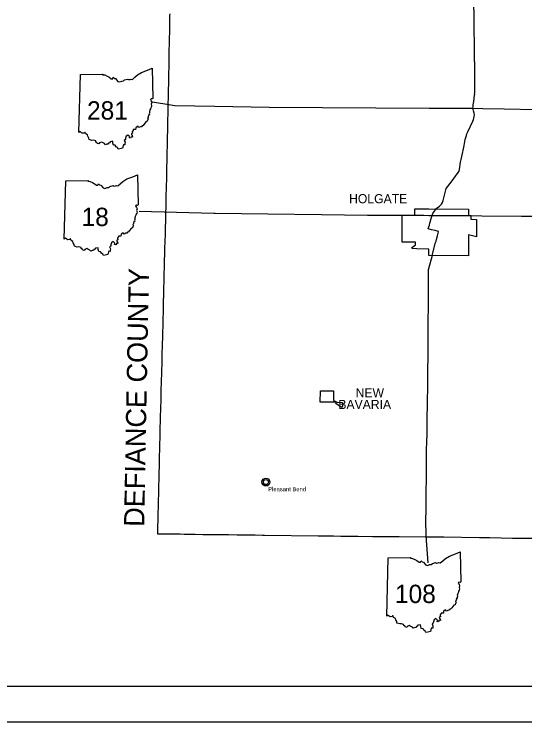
# Model space of a CAD drawing. Extents: x -62 to 810, y 0 to 440.
# Drawn here: x 166.9 to 310.9, y 0 to 199.3 of the extents above; entities that cross this region are included whole.
import ezdxf

# ---------------------------------------------------------------- set-up
doc = ezdxf.new("R2010")
doc.units = 0
for name, color, linetype in [('DV_X_Corp_Line', 7, 'Continuous'), ('GM_X_Adjacent_County_Text', 7, 'Continuous'), ('GM_X_Corporation_Text', 7, 'Continuous'), ('GM_X_County', 7, 'Continuous'), ('GM_X_State_Route', 7, 'Continuous'), ('PV_P_Text', 7, 'Continuous'), ('SH_Border', 7, 'Continuous'), ('SH_Cut_Line', 7, 'Continuous')]:
    doc.layers.add(name, color=color, linetype=linetype)

msp = doc.modelspace()

# ---------------------------------------------------------------- linework, layer by layer
at = {"layer": 'DV_X_Corp_Line'}
for points in [[(279.19, 133.31), (278.92, 133.53), (280.1, 134.39), (280.05, 135.06), (276.3, 135.11), (276.33, 142.7), (279.86, 142.69), (279.86, 144.51), (283.8, 144.52), (295.06, 144.43), (295.06, 142.58), (295.63, 142.57), (295.63, 141.54), (297.23, 141.51), (297.23, 136.6), (295.05, 137.18), (295.04, 135.75), (295.06, 131.26), (283.85, 131.34), (283.82, 133.16), (280.44, 133.26)], [(253.26, 93.23), (257.01, 93.23), (257.01, 90.5), (257.59, 90.25), (257.75, 90.17), (258, 90.01), (259.54, 89.99), (259.51, 88.92), (259.19, 88.57), (257.59, 89.68), (257.82, 90.01), (253.23, 90.06)]]:
    msp.add_lwpolyline(points, close=True, dxfattribs=at)
for radius in [1.12, 0.71]:
    msp.add_circle((237.91, 67.55), radius, dxfattribs=at)
at = {"layer": 'GM_X_County'}
msp.add_lwpolyline([(210.79, 199.39), (210.78, 198.9), (210.78, 198.36), (210.77, 197.7), (210.75, 196.78), (210.73, 195.73), (210.73, 195.48), (210.74, 195.3), (210.75, 195.11), (210.59, 188.38), (210.59, 188.18), (210.59, 187.72), (210.58, 187.41), (210.56, 186.61), (210.55, 186.35), (210.55, 186.22), (210.55, 186.05), (210.54, 185.84), (210.52, 185.04), (210.52, 184.66), (210.51, 184.14), (210.49, 183.01), (210.46, 181.7), (210.44, 180.62), (210.43, 179.89), (210.41, 179.2), (210.4, 178.55), (210.37, 177.22), (210.35, 176.42), (210.33, 175.26), (210.31, 174.68), (210.29, 173.89), (210.28, 172.95), (210.25, 171.58), (210.24, 171.06), (210.21, 169.71), (210.19, 168.69), (210.18, 168.07), (210.16, 167.47), (210.14, 166.03), (210.12, 165.32), (210.09, 163.95), (210.08, 163.49), (210.07, 163.16), (210.06, 162.58), (210.04, 161.51), (210.03, 161.1), (210.02, 160.71), (210.01, 160.11), (210, 159.66), (209.99, 159.15), (209.98, 158.78), (209.97, 158.67), (209.97, 158.58), (209.97, 158.57), (209.97, 158.47), (209.97, 158.39), (209.97, 158.35), (209.97, 158.3), (209.96, 158.18), (209.96, 158.13), (209.96, 157.88), (209.92, 156.28), (209.91, 155.64), (209.9, 155.31), (209.89, 154.56), (209.86, 152.94), (209.85, 152.29), (209.83, 151.52), (209.81, 151.22), (209.81, 151.12), (209.81, 151.04), (209.79, 150.53), (209.76, 149.75), (209.75, 148.82), (209.73, 148.21), (209.71, 146.96), (209.7, 146.22), (209.67, 144.67), (209.64, 143.65), (209.64, 143.28), (209.63, 142.74), (209.62, 142.38), (209.59, 141.49), (209.57, 140.57), (209.55, 139.74), (209.53, 139.21), (209.52, 138.71), (209.5, 138.14), (209.49, 137.47), (209.47, 136.51), (209.45, 136.09), (209.42, 135.28), (209.37, 133.38), (209.33, 131.98), (209.31, 131.42), (209.28, 130.25), (209.24, 128.79), (209.23, 128.54), (209.22, 128.38), (209.21, 128.01), (209.2, 127.47), (209.18, 126.79), (209.15, 125.69), (209.13, 124.51), (209.12, 123.95), (209.09, 122.47), (209.05, 120.78), (209.03, 120.05), (209.02, 119.65), (209.01, 119.57), (209.01, 119.46), (209, 119.11), (208.98, 118.08), (208.96, 117.38), (208.94, 116.4), (208.92, 115.39), (208.89, 113.53), (208.85, 111.96), (208.82, 111.23), (208.78, 109.94), (208.73, 108.04), (208.69, 106.64), (208.67, 106.03), (208.67, 105.86), (208.65, 105.21), (208.62, 104.3), (208.57, 101.83), (208.54, 100.63), (208.51, 99.13), (208.49, 98.5), (208.48, 98.3), (208.45, 97.36), (208.43, 96.8), (208.43, 96.79), (208.41, 96.31), (208.38, 95.21), (208.34, 93.86), (208.31, 92.54), (208.26, 90.67), (208.25, 90.53), (208.2, 88.43), (208.17, 87.47), (208.15, 86.57), (208.13, 85.92), (208.1, 85.18), (208.08, 84.09), (208.06, 83.39), (208.06, 83.15), (208.06, 82.92), (208.05, 82.57), (208.04, 82.18), (208.03, 81.98), (208.03, 81.74), (208.02, 81.51), (208.01, 81.12), (208, 80.56), (207.99, 80.24), (207.97, 79.66), (207.97, 79.36), (207.96, 78.96), (207.95, 78.4), (207.93, 77.97), (207.93, 77.81), (207.92, 77.27), (207.9, 76.7), (207.89, 76.34), (207.88, 75.96), (207.87, 75.58), (207.87, 75.49), (207.87, 75.14), (207.86, 74.74), (207.85, 74.31), (207.84, 73.91), (207.83, 73.5), (207.81, 72.78), (207.8, 72.4), (207.79, 71.89), (207.78, 71.45), (207.77, 70.8), (207.75, 70.16), (207.73, 69.5), (207.72, 68.99), (207.72, 68.66), (207.71, 68.46), (207.7, 68.22), (207.7, 68.13), (207.7, 68.11), (207.7, 68.06), (207.7, 68.03), (207.7, 67.75), (207.68, 67.08), (207.67, 66.71), (207.66, 66.34), (207.65, 65.82), (207.65, 65.64), (207.64, 65.45), (207.63, 65.13), (207.62, 64.52), (207.61, 64.12), (207.6, 63.67), (207.58, 62.94), (207.57, 62.5), (207.56, 62.16), (207.55, 61.91), (207.54, 61.3), (207.52, 60.76), (207.5, 59.92), (207.49, 59.57), (207.47, 58.74), (207.47, 58.62), (207.45, 57.88), (207.44, 57.59), (207.42, 56.92), (207.42, 56.63), (207.42, 56.42), (207.41, 56.19), (207.4, 55.71), (207.4, 55.52), (207.38, 54.94), (207.37, 54.55), (207.36, 53.88), (207.35, 53.35), (207.34, 52.98), (207.91, 52.98), (210.72, 52.94), (213.71, 52.91), (214.91, 52.89), (215.86, 52.87), (218.02, 52.84), (220.17, 52.81), (221.71, 52.78), (225.59, 52.74), (226.06, 52.74), (227.37, 52.73), (229.8, 52.7), (230.97, 52.69), (231.58, 52.68), (232.28, 52.67), (234.9, 52.65), (236.95, 52.61), (237.54, 52.61), (252.62, 52.42), (256.97, 52.37), (259.07, 52.34), (263.51, 52.28), (263.59, 52.28), (263.67, 52.28), (263.82, 52.28), (267.99, 52.23), (275.46, 52.17), (283.06, 52.11), (284.18, 52.11), (288.1, 52.08), (298.1, 51.96), (301, 51.9), (304.18, 51.82), (307.45, 51.77), (308.29, 51.76), (310.77, 51.73), (313.34, 51.7)], dxfattribs=at)
at = {"layer": 'GM_X_State_Route'}
msp.add_line((296.73, 185.88), (296.75, 177.12), dxfattribs=at)
for points in [[(296.73, 185.88), (296.73, 187.78), (296.61, 198.1), (296.52, 202.86), (296.5, 204.59), (296.42, 211.89), (296.39, 214.54), (296.33, 217.94), (296.33, 217.94)], [(296.28, 172.8), (296.33, 173.2), (296.37, 173.8), (296.49, 174.76), (296.74, 176.48), (296.77, 176.81), (296.75, 177.12)], [(205.99, 174.64), (211.07, 173.75), (212.25, 173.57), (223.56, 173.38), (238.86, 173.11), (253.82, 173.03), (268.89, 172.94), (283.91, 172.86), (296.28, 172.8)], [(286.02, 144.55), (286.23, 144.77), (286.82, 145.22), (287.37, 145.84), (287.66, 146.23), (287.87, 146.81), (288.76, 150.18), (290.14, 151.97), (292.08, 154.69), (292.35, 155.11), (292.49, 155.55), (292.77, 157.65), (292.93, 158.34), (293.33, 160.07), (293.65, 161.39), (293.81, 162.31), (294.1, 164.02), (294.27, 164.56), (294.45, 165.1), (294.58, 165.66), (294.83, 166.22), (296.25, 169.15), (296.42, 169.62), (296.52, 170.04), (296.62, 170.51), (296.67, 171.02), (296.6, 171.48), (296.44, 172.08), (296.28, 172.8)], [(296.28, 172.8), (299.02, 172.75), (305.07, 172.65), (314.15, 172.51), (329.25, 172.33), (342.44, 172.14)], [(202.18, 143.84), (223.28, 143.31), (223.64, 143.3), (238.42, 143.05), (253.55, 142.88), (266.57, 142.73), (268.03, 142.74), (268.67, 142.73), (275.77, 142.7)], [(284.16, 140.45), (284.24, 140.75), (284.54, 141.77), (284.77, 142.66), (284.92, 143.14), (285.11, 143.5), (285.67, 144.17), (286.01, 144.55), (286.02, 144.55)], [(275.77, 142.7), (276.37, 142.7)], [(276.37, 142.7), (277.35, 142.69), (277.42, 142.69)], [(277.42, 142.69), (279.53, 142.68), (279.82, 142.68)], [(279.82, 142.68), (280.51, 142.68), (281.53, 142.67), (282.44, 142.67), (283.87, 142.66), (284.77, 142.66), (285.76, 142.65), (286.79, 142.64), (287.79, 142.64), (290.03, 142.62), (291.71, 142.61)], [(291.71, 142.61), (295.18, 142.58)], [(295.18, 142.58), (295.79, 142.57)], [(295.79, 142.57), (298.8, 142.55), (309.97, 142.42), (314.08, 142.4), (342.7, 141.81)], [(283.69, 138.83), (283.86, 139.43), (283.99, 139.85), (284.16, 140.45)], [(286.56, 138), (286.58, 138.1), (285.59, 138.35), (284.62, 138.6), (283.69, 138.83)], [(284.85, 131.48), (284.85, 131.48), (284.9, 131.68), (285.76, 134.98), (285.87, 135.4), (286, 135.87), (286.27, 136.9), (286.56, 138), (286.56, 138)], [(283.62, 44.8), (283.04, 52.41), (283.01, 57), (283.04, 59.53), (283.07, 62.43), (283.13, 66.28), (283.14, 67.07), (283.15, 69.02), (283.18, 73.51), (283.22, 77.27), (283.25, 78.17), (283.33, 81.65), (283.34, 82.25), (283.39, 85.54), (283.46, 89.35), (283.47, 89.75), (283.53, 94.82), (283.56, 97.33), (283.64, 104.63), (283.68, 108.93), (283.69, 112.99), (283.71, 116.92), (283.75, 121.64), (283.79, 127.3), (283.79, 127.41), (283.84, 127.65), (284.85, 131.48)]]:
    msp.add_lwpolyline(points, dxfattribs=at)
at = {"layer": 'PV_P_Text'}
for p, q in [((185.18, 165.98), (185.64, 182.36)), ((185.18, 165.98), (185.64, 182.36)), ((181.04, 135.99), (181.5, 152.36)), ((181.04, 135.99), (181.5, 152.36)), ((271.96, 29.81), (272.42, 46.18)), ((271.96, 29.81), (272.42, 46.18))]:
    msp.add_line(p, q, dxfattribs=at)
for points in [[(185.64, 182.36), (191.99, 182.46), (191.89, 182.27), (192.49, 182.22), (193.13, 181.87), (193.67, 181.65), (194.33, 181.13), (194.72, 181.14), (194.89, 181.57), (195.19, 181.24), (195.55, 181.18), (196.17, 180.39), (196.68, 180.22), (197.29, 180.49), (197.75, 180.54), (198.08, 180.8), (198.95, 181.03), (199.2, 180.89), (199.66, 180.92), (199.89, 181.02), (200.29, 180.93), (201, 181.53), (201.73, 182.23), (202.85, 182.89), (204.53, 183.52), (205.86, 184.08), (206.05, 175.58)], [(185.64, 182.36), (191.99, 182.46), (191.89, 182.27), (192.49, 182.22), (193.13, 181.87), (193.67, 181.65), (194.33, 181.13), (194.72, 181.14), (194.89, 181.57), (195.19, 181.24), (195.55, 181.18), (196.17, 180.39), (196.68, 180.22), (197.29, 180.49), (197.75, 180.54), (198.08, 180.8), (198.95, 181.03), (199.2, 180.89), (199.66, 180.92), (199.89, 181.02), (200.29, 180.93), (201, 181.53), (201.73, 182.23), (202.85, 182.89), (204.53, 183.52), (205.86, 184.08), (206.05, 175.58)], [(206.05, 175.58), (205.85, 175.46), (205.55, 175.52), (205.34, 175.28), (205.6, 174.88), (205.72, 174.46), (205.61, 174), (205.71, 173.62), (205.64, 173.3), (205.45, 172.98), (205.38, 172.68), (205.22, 172.36), (205.24, 172.18), (205.08, 172.04), (205.11, 171.51), (205.03, 171.21), (205.06, 170.96), (204.81, 170.89), (204.86, 170.68), (204.7, 170.52), (204.74, 170.24), (204.56, 170.06), (204.73, 169.71), (204.59, 169.59), (204.47, 169.16), (204.15, 169.07), (203.5, 168.28), (203.28, 167.98), (203.02, 167.9), (202.88, 167.6), (202.56, 167.6), (202.09, 167.38), (201.78, 167.75), (201.24, 167.31), (201.18, 166.8), (200.49, 166.81), (200.52, 166.55), (200.37, 166.48), (200.23, 166.22), (200.31, 165.76), (199.99, 165.64), (200.03, 165.38), (200.23, 165.21), (200.32, 164.7), (199.98, 164.81), (199.7, 164.38), (199.42, 164.48), (199.51, 164.84), (199.03, 165.28), (198.57, 164.93), (198.33, 164.37), (198.33, 163.99), (197.99, 163.77), (198.21, 163.23), (198.17, 162.87), (198.17, 162.52), (197.75, 162.53), (197.49, 161.59)], [(206.05, 175.58), (205.85, 175.46), (205.55, 175.52), (205.34, 175.28), (205.6, 174.88), (205.72, 174.46), (205.61, 174), (205.71, 173.62), (205.64, 173.3), (205.45, 172.98), (205.38, 172.68), (205.22, 172.36), (205.24, 172.18), (205.08, 172.04), (205.11, 171.51), (205.03, 171.21), (205.06, 170.96), (204.81, 170.89), (204.86, 170.68), (204.7, 170.52), (204.74, 170.24), (204.56, 170.06), (204.73, 169.71), (204.59, 169.59), (204.47, 169.16), (204.15, 169.07), (203.5, 168.28), (203.28, 167.98), (203.02, 167.9), (202.88, 167.6), (202.56, 167.6), (202.09, 167.38), (201.78, 167.75), (201.24, 167.31), (201.18, 166.8), (200.49, 166.81), (200.52, 166.55), (200.37, 166.48), (200.23, 166.22), (200.31, 165.76), (199.99, 165.64), (200.03, 165.38), (200.23, 165.21), (200.32, 164.7), (199.98, 164.81), (199.7, 164.38), (199.42, 164.48), (199.51, 164.84), (199.03, 165.28), (198.57, 164.93), (198.33, 164.37), (198.33, 163.99), (197.99, 163.77), (198.21, 163.23), (198.17, 162.87), (198.17, 162.52), (197.75, 162.53), (197.49, 161.59)], [(197.49, 161.59), (196.75, 161.41), (196.23, 161.3), (196.05, 161.73), (195.68, 161.95), (195.44, 162.38), (194.91, 162.44), (194.79, 163.03), (194.73, 163.51), (194.01, 163.39), (193.81, 163.1), (193.55, 163.02), (193.4, 162.73), (193.06, 162.7), (192.68, 162.56), (192.44, 162.85), (191.82, 163.14), (191.55, 163.29), (190.97, 163.06), (190.84, 162.79), (190.38, 162.91), (190.28, 163.21), (190, 163.31), (189.94, 163.63), (189.34, 163.81), (188.89, 163.74), (188.09, 164), (188.04, 164.43), (187.76, 164.95), (187.62, 165.31), (187.12, 165.59), (187.01, 166.02), (186.85, 166.01), (186.7, 165.84), (186.14, 165.76), (185.91, 165.93), (185.6, 166.23), (185.18, 165.98)], [(197.49, 161.59), (196.75, 161.41), (196.23, 161.3), (196.05, 161.73), (195.68, 161.95), (195.44, 162.38), (194.91, 162.44), (194.79, 163.03), (194.73, 163.51), (194.01, 163.39), (193.81, 163.1), (193.55, 163.02), (193.4, 162.73), (193.06, 162.7), (192.68, 162.56), (192.44, 162.85), (191.82, 163.14), (191.55, 163.29), (190.97, 163.06), (190.84, 162.79), (190.38, 162.91), (190.28, 163.21), (190, 163.31), (189.94, 163.63), (189.34, 163.81), (188.89, 163.74), (188.09, 164), (188.04, 164.43), (187.76, 164.95), (187.62, 165.31), (187.12, 165.59), (187.01, 166.02), (186.85, 166.01), (186.7, 165.84), (186.14, 165.76), (185.91, 165.93), (185.6, 166.23), (185.18, 165.98)], [(181.5, 152.36), (187.86, 152.47), (187.76, 152.27), (188.36, 152.23), (188.99, 151.88), (189.53, 151.66), (190.19, 151.14), (190.58, 151.14), (190.75, 151.57), (191.05, 151.24), (191.41, 151.18), (192.03, 150.4), (192.54, 150.23), (193.15, 150.5), (193.61, 150.54), (193.95, 150.81), (194.82, 151.03), (195.06, 150.9), (195.52, 150.93), (195.75, 151.03), (196.16, 150.94), (196.87, 151.53), (197.6, 152.23), (198.72, 152.9), (200.39, 153.52), (201.72, 154.08), (201.91, 145.59)], [(181.5, 152.36), (187.86, 152.47), (187.76, 152.27), (188.36, 152.23), (188.99, 151.88), (189.53, 151.66), (190.19, 151.14), (190.58, 151.14), (190.75, 151.57), (191.05, 151.24), (191.41, 151.18), (192.03, 150.4), (192.54, 150.23), (193.15, 150.5), (193.61, 150.54), (193.95, 150.81), (194.82, 151.03), (195.06, 150.9), (195.52, 150.93), (195.75, 151.03), (196.16, 150.94), (196.87, 151.53), (197.6, 152.23), (198.72, 152.9), (200.39, 153.52), (201.72, 154.08), (201.91, 145.59)], [(201.91, 145.59), (201.71, 145.47), (201.41, 145.52), (201.2, 145.29), (201.46, 144.89), (201.58, 144.47), (201.47, 144.01), (201.58, 143.62), (201.51, 143.3), (201.31, 142.99), (201.25, 142.68), (201.09, 142.36), (201.1, 142.18), (200.94, 142.04), (200.97, 141.51), (200.89, 141.22), (200.92, 140.96), (200.67, 140.9), (200.73, 140.69), (200.57, 140.52), (200.6, 140.24), (200.42, 140.07), (200.6, 139.71), (200.45, 139.6), (200.34, 139.16), (200.01, 139.08), (199.37, 138.28), (199.14, 137.98), (198.88, 137.91), (198.74, 137.6), (198.43, 137.6), (197.95, 137.39), (197.64, 137.75), (197.1, 137.31), (197.04, 136.8), (196.36, 136.82), (196.38, 136.56), (196.23, 136.48), (196.09, 136.23), (196.17, 135.77), (195.85, 135.65), (195.89, 135.38), (196.09, 135.22), (196.19, 134.71), (195.85, 134.81), (195.57, 134.38), (195.28, 134.48), (195.37, 134.85), (194.89, 135.28), (194.43, 134.93), (194.19, 134.37), (194.19, 134), (193.85, 133.77), (194.07, 133.24), (194.03, 132.87), (194.04, 132.52), (193.61, 132.53), (193.35, 131.59)], [(201.91, 145.59), (201.71, 145.47), (201.41, 145.52), (201.2, 145.29), (201.46, 144.89), (201.58, 144.47), (201.47, 144.01), (201.58, 143.62), (201.51, 143.3), (201.31, 142.99), (201.25, 142.68), (201.09, 142.36), (201.1, 142.18), (200.94, 142.04), (200.97, 141.51), (200.89, 141.22), (200.92, 140.96), (200.67, 140.9), (200.73, 140.69), (200.57, 140.52), (200.6, 140.24), (200.42, 140.07), (200.6, 139.71), (200.45, 139.6), (200.34, 139.16), (200.01, 139.08), (199.37, 138.28), (199.14, 137.98), (198.88, 137.91), (198.74, 137.6), (198.43, 137.6), (197.95, 137.39), (197.64, 137.75), (197.1, 137.31), (197.04, 136.8), (196.36, 136.82), (196.38, 136.56), (196.23, 136.48), (196.09, 136.23), (196.17, 135.77), (195.85, 135.65), (195.89, 135.38), (196.09, 135.22), (196.19, 134.71), (195.85, 134.81), (195.57, 134.38), (195.28, 134.48), (195.37, 134.85), (194.89, 135.28), (194.43, 134.93), (194.19, 134.37), (194.19, 134), (193.85, 133.77), (194.07, 133.24), (194.03, 132.87), (194.04, 132.52), (193.61, 132.53), (193.35, 131.59)], [(193.35, 131.59), (192.61, 131.41), (192.1, 131.31), (191.91, 131.73), (191.55, 131.96), (191.31, 132.39), (190.78, 132.45), (190.65, 133.04), (190.59, 133.52), (189.87, 133.4), (189.67, 133.11), (189.42, 133.03), (189.27, 132.73), (188.92, 132.71), (188.54, 132.57), (188.3, 132.86), (187.68, 133.15), (187.41, 133.3), (186.83, 133.07), (186.71, 132.79), (186.25, 132.91), (186.14, 133.22), (185.86, 133.31), (185.8, 133.64), (185.21, 133.81), (184.75, 133.74), (183.95, 134), (183.9, 134.43), (183.63, 134.96), (183.48, 135.32), (182.98, 135.6), (182.88, 136.03), (182.71, 136.02), (182.56, 135.84), (182, 135.76), (181.78, 135.94), (181.46, 136.24), (181.04, 135.99)], [(193.35, 131.59), (192.61, 131.41), (192.1, 131.31), (191.91, 131.73), (191.55, 131.96), (191.31, 132.39), (190.78, 132.45), (190.65, 133.04), (190.59, 133.52), (189.87, 133.4), (189.67, 133.11), (189.42, 133.03), (189.27, 132.73), (188.92, 132.71), (188.54, 132.57), (188.3, 132.86), (187.68, 133.15), (187.41, 133.3), (186.83, 133.07), (186.71, 132.79), (186.25, 132.91), (186.14, 133.22), (185.86, 133.31), (185.8, 133.64), (185.21, 133.81), (184.75, 133.74), (183.95, 134), (183.9, 134.43), (183.63, 134.96), (183.48, 135.32), (182.98, 135.6), (182.88, 136.03), (182.71, 136.02), (182.56, 135.84), (182, 135.76), (181.78, 135.94), (181.46, 136.24), (181.04, 135.99)], [(272.42, 46.18), (278.77, 46.29), (278.67, 46.09), (279.27, 46.05), (279.91, 45.7), (280.44, 45.48), (281.1, 44.96), (281.5, 44.96), (281.66, 45.39), (281.97, 45.06), (282.32, 45), (282.94, 44.22), (283.45, 44.05), (284.07, 44.31), (284.53, 44.36), (284.86, 44.62), (285.73, 44.85), (285.97, 44.72), (286.44, 44.74), (286.67, 44.84), (287.07, 44.75), (287.78, 45.35), (288.51, 46.05), (289.63, 46.71), (291.31, 47.34), (292.63, 47.9), (292.82, 39.4)], [(272.42, 46.18), (278.77, 46.29), (278.67, 46.09), (279.27, 46.05), (279.91, 45.7), (280.44, 45.48), (281.1, 44.96), (281.5, 44.96), (281.66, 45.39), (281.97, 45.06), (282.32, 45), (282.94, 44.22), (283.45, 44.05), (284.07, 44.31), (284.53, 44.36), (284.86, 44.62), (285.73, 44.85), (285.97, 44.72), (286.44, 44.74), (286.67, 44.84), (287.07, 44.75), (287.78, 45.35), (288.51, 46.05), (289.63, 46.71), (291.31, 47.34), (292.63, 47.9), (292.82, 39.4)], [(292.82, 39.4), (292.63, 39.29), (292.32, 39.34), (292.12, 39.1), (292.37, 38.71), (292.49, 38.29), (292.39, 37.82), (292.49, 37.44), (292.42, 37.12), (292.23, 36.8), (292.16, 36.5), (292, 36.18), (292.01, 36), (291.86, 35.86), (291.89, 35.33), (291.81, 35.03), (291.83, 34.78), (291.58, 34.71), (291.64, 34.5), (291.48, 34.34), (291.51, 34.06), (291.33, 33.88), (291.51, 33.53), (291.37, 33.41), (291.25, 32.98), (290.93, 32.89), (290.28, 32.1), (290.05, 31.8), (289.8, 31.73), (289.66, 31.42), (289.34, 31.42), (288.86, 31.2), (288.56, 31.57), (288.01, 31.13), (287.95, 30.62), (287.27, 30.63), (287.3, 30.38), (287.14, 30.3), (287, 30.04), (287.08, 29.58), (286.76, 29.47), (286.8, 29.2), (287.01, 29.04), (287.1, 28.53), (286.76, 28.63), (286.48, 28.2), (286.19, 28.3), (286.29, 28.66), (285.8, 29.1), (285.35, 28.75), (285.11, 28.19), (285.1, 27.81), (284.76, 27.59), (284.98, 27.05), (284.94, 26.69), (284.95, 26.34), (284.52, 26.35), (284.26, 25.41)], [(292.82, 39.4), (292.63, 39.29), (292.32, 39.34), (292.12, 39.1), (292.37, 38.71), (292.49, 38.29), (292.39, 37.82), (292.49, 37.44), (292.42, 37.12), (292.23, 36.8), (292.16, 36.5), (292, 36.18), (292.01, 36), (291.86, 35.86), (291.89, 35.33), (291.81, 35.03), (291.83, 34.78), (291.58, 34.71), (291.64, 34.5), (291.48, 34.34), (291.51, 34.06), (291.33, 33.88), (291.51, 33.53), (291.37, 33.41), (291.25, 32.98), (290.93, 32.89), (290.28, 32.1), (290.05, 31.8), (289.8, 31.73), (289.66, 31.42), (289.34, 31.42), (288.86, 31.2), (288.56, 31.57), (288.01, 31.13), (287.95, 30.62), (287.27, 30.63), (287.3, 30.38), (287.14, 30.3), (287, 30.04), (287.08, 29.58), (286.76, 29.47), (286.8, 29.2), (287.01, 29.04), (287.1, 28.53), (286.76, 28.63), (286.48, 28.2), (286.19, 28.3), (286.29, 28.66), (285.8, 29.1), (285.35, 28.75), (285.11, 28.19), (285.1, 27.81), (284.76, 27.59), (284.98, 27.05), (284.94, 26.69), (284.95, 26.34), (284.52, 26.35), (284.26, 25.41)], [(284.26, 25.41), (283.52, 25.23), (283.01, 25.12), (282.83, 25.55), (282.46, 25.78), (282.22, 26.21), (281.69, 26.27), (281.57, 26.86), (281.51, 27.33), (280.78, 27.22), (280.59, 26.92), (280.33, 26.84), (280.18, 26.55), (279.83, 26.52), (279.46, 26.39), (279.21, 26.67), (278.6, 26.97), (278.32, 27.12), (277.74, 26.88), (277.62, 26.61), (277.16, 26.73), (277.05, 27.04), (276.78, 27.13), (276.71, 27.45), (276.12, 27.63), (275.66, 27.56), (274.86, 27.82), (274.81, 28.25), (274.54, 28.77), (274.4, 29.14), (273.89, 29.41), (273.79, 29.85), (273.63, 29.83), (273.48, 29.66), (272.92, 29.58), (272.69, 29.75), (272.37, 30.05), (271.96, 29.81)], [(284.26, 25.41), (283.52, 25.23), (283.01, 25.12), (282.83, 25.55), (282.46, 25.78), (282.22, 26.21), (281.69, 26.27), (281.57, 26.86), (281.51, 27.33), (280.78, 27.22), (280.59, 26.92), (280.33, 26.84), (280.18, 26.55), (279.83, 26.52), (279.46, 26.39), (279.21, 26.67), (278.6, 26.97), (278.32, 27.12), (277.74, 26.88), (277.62, 26.61), (277.16, 26.73), (277.05, 27.04), (276.78, 27.13), (276.71, 27.45), (276.12, 27.63), (275.66, 27.56), (274.86, 27.82), (274.81, 28.25), (274.54, 28.77), (274.4, 29.14), (273.89, 29.41), (273.79, 29.85), (273.63, 29.83), (273.48, 29.66), (272.92, 29.58), (272.69, 29.75), (272.37, 30.05), (271.96, 29.81)]]:
    msp.add_lwpolyline(points, dxfattribs=at)
at = {"layer": 'SH_Border'}
msp.add_lwpolyline([(30, 430), (670, 430), (670, 10), (30, 10)], close=True, dxfattribs=at)
at = {"layer": 'SH_Cut_Line'}
msp.add_lwpolyline([(0, 0), (680, 0), (680, 440), (0, 440)], close=True, dxfattribs=at)

# ---------------------------------------------------------------- texts
at = {"layer": 'GM_X_Adjacent_County_Text'}
msp.add_text('DEFIANCE COUNTY', height=5.7, rotation=88.9256, dxfattribs=at).set_placement((203.6, 54.88))
at = {"layer": 'GM_X_Corporation_Text'}
for s, height, p in [('HOLGATE', 2.565, (261.36, 146.07)), ('NEW', 2.565, (263.21, 91.39)), ('BAVARIA', 2.565, (258.33, 88.12)), ('Pleasant Bend', 1.1875, (238.56, 64.95))]:
    msp.add_text(s, height=height, rotation=0, dxfattribs=at).set_placement(p)
at = {"layer": 'PV_P_Text'}
for s, p in [('281', (187.49, 169.63)), ('18', (185.96, 139.64)), ('108', (274.29, 33.46))]:
    msp.add_text(s, height=5.162, dxfattribs=at).set_placement(p)

doc.saveas('drawing.dxf')
